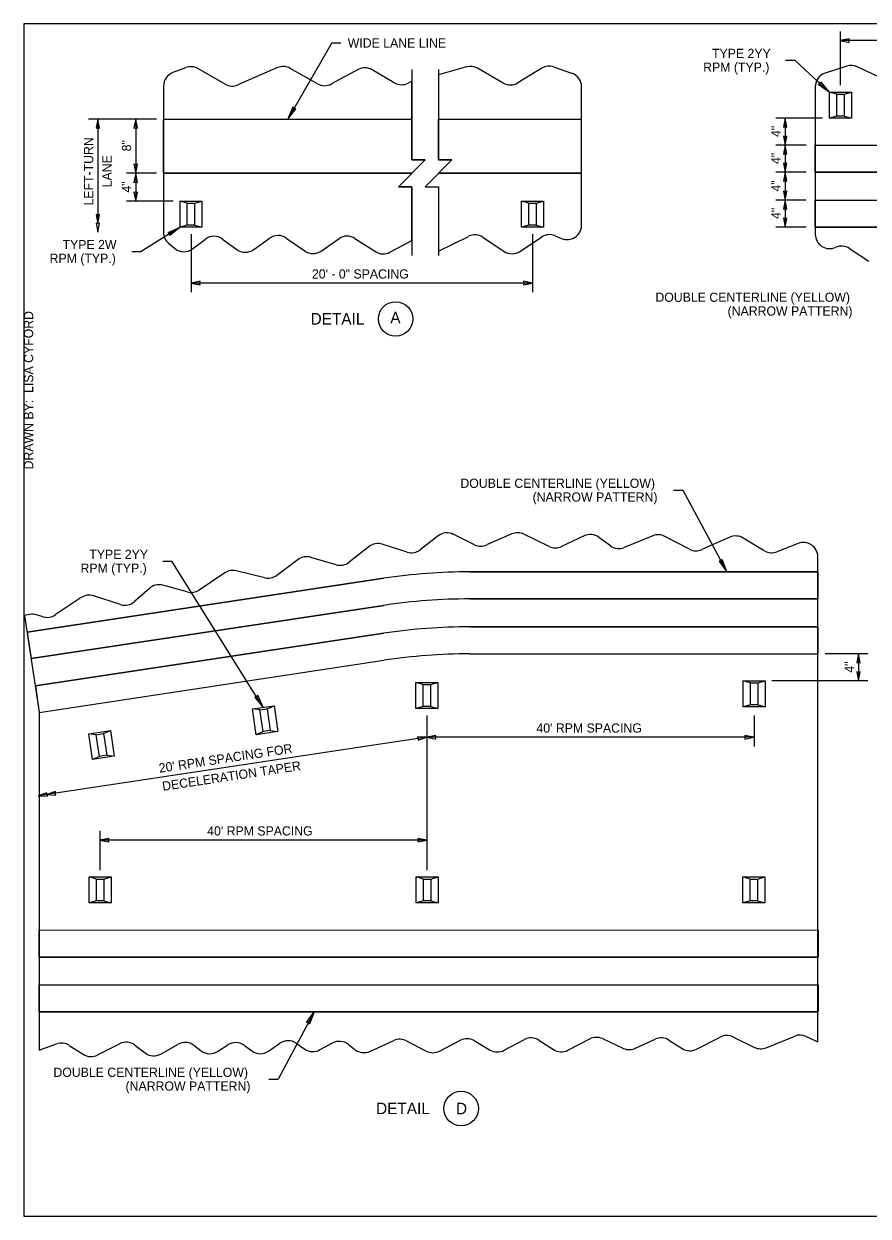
# Model space of a CAD drawing. Extents: x 99862 to 104211, y 98939 to 105076.
# Drawn here: x 99862 to 101332, y 103000 to 105076 of the extents above; entities that cross this region are included whole.
import ezdxf

# ---------------------------------------------------------------- set-up
doc = ezdxf.new("R2010")
doc.units = 0
for name, color, linetype in [('Level 1', 7, 'Continuous'), ('Level 10', 7, 'Continuous'), ('Level 15', 7, 'Continuous'), ('Level 18', 7, 'Continuous'), ('Level 20', 7, 'Continuous'), ('Level 22', 7, 'Continuous'), ('Level 50', 7, 'Continuous'), ('Level 60', 7, 'Continuous'), ('Level 62', 7, 'Continuous'), ('Level 9', 7, 'Continuous')]:
    doc.layers.add(name, color=color, linetype=linetype)

msp = doc.modelspace()

# ---------------------------------------------------------------- linework, layer by layer
at = {"layer": 'Level 1'}
msp.add_lwpolyline([(99862, 102999.5), (103151, 102999.5), (103151, 105075.5), (99862, 105075.5)], close=True, dxfattribs=at)
at = {"layer": 'Level 10'}
for p, q in [((100105, 104909.5), (100537.2, 104909.5)), ((100105, 104815.3), (100105, 104909.5)), ((100583.7, 104909.5), (100832.8, 104909.6)), ((100537.2, 104815.3), (100105, 104815.3)), ((100832.8, 104815.3), (100583.7, 104815.3)), ((101239.7, 104768.6), (101541.9, 104768.7)), ((101239.7, 104721.5), (101239.7, 104768.6)), ((101541.9, 104721.6), (101239.7, 104721.5)), ((100638.1, 104074.2), (101245, 104074.3)), ((100638.1, 103978.6), (101245, 103978.7)), ((99888.7, 103497.7), (101245, 103497.8)), ((99888.7, 103450.8), (99888.7, 103497.7)), ((101245, 103497.8), (101245, 103450.6)), ((100679.8, 103450.7), (99888.7, 103450.8)), ((101245, 103450.6), (100679.8, 103450.7)), ((99888.7, 103402.1), (101245, 103402.2)), ((99888.7, 103355), (99888.7, 103402.1)), ((101245, 103402.2), (101245, 103355.1)), ((101245, 103355.1), (99888.7, 103355))]:
    msp.add_line(p, q, dxfattribs=at)
for points in [[(100537.2, 104909.5), (100537.2, 104838.5), (100560.4, 104838.5), (100537.2, 104815.3)], [(100583.7, 104815.3), (100606.9, 104838.5), (100583.7, 104838.5), (100583.7, 104909.5)], [(101245, 104074.3), (101245, 104121.4), (100638.1, 104121.3)], [(100488.8, 104110.1), (99867.6, 104016.3), (99874.6, 103970.2), (100488.8, 104063)], [(100488.8, 104014.5), (99881.8, 103922.8), (99888.7, 103876.7), (100488.8, 103967.4)], [(101245, 103978.7), (101245, 104025.8), (100638.1, 104025.7)]]:
    msp.add_lwpolyline(points, dxfattribs=at)
msp.add_lwpolyline([(101239.7, 104864.2), (101541.9, 104864.3), (101541.9, 104864), (101541.9, 104850), (101565.1, 104850), (101532.3, 104817.2), (101239.7, 104817.1)], close=True, dxfattribs=at)
for centre in [(100638.2, 103121.3), (100638.2, 103074.2), (100638.2, 103025.7), (100638.2, 102978.6)]:
    msp.add_arc(centre, 1000, 90.0065, 98.5919, dxfattribs=at)
at = {"layer": 'Level 15'}
for p, q in [((101282.9, 105062.4), (101282.9, 104968.6)), ((101852.2, 105046.4), (101282.9, 105046.4)), ((100397.7, 105042.2), (100321.1, 104909.5)), ((100397.7, 105042.2), (100413.7, 105042.2)), ((101187.9, 105012), (101203.9, 105012)), ((101263.8, 104956.7), (101203.9, 105012)), ((100093, 104909.5), (99974.5, 104909.5)), ((99990.5, 104909.5), (99990.5, 104727.8)), ((100056.5, 104909.5), (100056.5, 104815.3)), ((101252.4, 104911.3), (101171.2, 104911.3)), ((101187.2, 104911.3), (101187.2, 104864.2)), ((101223.7, 104864.2), (101171.2, 104864.2)), ((101187.2, 104864.2), (101187.2, 104817.1)), ((100093, 104815.3), (100040.5, 104815.3)), ((100056.5, 104815.3), (100056.5, 104766.8)), ((101223.7, 104817.1), (101171.2, 104817.1)), ((101187.2, 104817.1), (101187.2, 104768.6)), ((100121.7, 104766.8), (100040.5, 104766.8)), ((101223.7, 104768.6), (101171.2, 104768.6)), ((101187.2, 104768.6), (101187.2, 104721.5)), ((100133.7, 104721.5), (100066, 104679.2)), ((101223.7, 104721.5), (101171.2, 104721.5)), ((100152.8, 104709.5), (100152.8, 104608.1)), ((100747.3, 104709.5), (100747.3, 104608.1)), ((100050, 104679.2), (100066, 104679.2)), ((100747.3, 104624.1), (100152.8, 104624.1)), ((100993.1, 104263.6), (101009.1, 104263.6)), ((101009.1, 104263.6), (101085.8, 104121.4)), ((100103.7, 104139.8), (100119.7, 104139.8)), ((100278.4, 103885.4), (100119.7, 104139.8)), ((101331, 103978.7), (101257, 103978.7)), ((101315, 103978.7), (101315, 103931.6)), ((101331, 103931.6), (101164.3, 103931.6)), ((100563.2, 103871.4), (100563.2, 103602.1)), ((101133.2, 103871.4), (101133.2, 103817.4)), ((100563.2, 103833.4), (99886.8, 103731.2)), ((101132.6, 103833.4), (100563.2, 103833.4)), ((101132.6, 103833.4), (100682.2, 103833.4)), ((99993.9, 103670.3), (99993.9, 103602.1)), ((100563.2, 103654.3), (99993.9, 103654.3)), ((100367.5, 103355), (100304.4, 103238)), ((100288.4, 103238), (100304.4, 103238))]:
    msp.add_line(p, q, dxfattribs=at)
for points in [[(101282.9, 105046.4), (101298.6, 105043.3), (101297.9, 105046.4), (101298.6, 105049.4)], [(101263.8, 104956.7), (101245, 104970), (101247.8, 104971.5), (101249, 104974.4)], [(100321.1, 104909.5), (100335.1, 104927.8), (100332, 104928.4), (100329.9, 104930.8)], [(99990.5, 104909.5), (99987.4, 104893.7), (99990.5, 104894.5), (99993.6, 104893.7)], [(100056.5, 104909.5), (100053.4, 104893.7), (100056.5, 104894.5), (100059.6, 104893.7)], [(101187.2, 104911.3), (101184.1, 104895.6), (101187.2, 104896.3), (101190.3, 104895.6)], [(101187.2, 104864.2), (101190.3, 104880), (101187.2, 104879.2), (101184.1, 104880)], [(101187.2, 104864.2), (101184.1, 104848.5), (101187.2, 104849.2), (101190.3, 104848.5)], [(100056.5, 104815.3), (100059.6, 104831), (100056.5, 104830.3), (100053.4, 104831)], [(101187.2, 104817.1), (101190.3, 104832.9), (101187.2, 104832.1), (101184.1, 104832.9)], [(100056.5, 104815.3), (100053.4, 104799.5), (100056.5, 104800.3), (100059.6, 104799.5)], [(101187.2, 104817.1), (101184.1, 104801.4), (101187.2, 104802.1), (101190.3, 104801.4)], [(100056.5, 104766.8), (100059.6, 104782.5), (100056.5, 104781.8), (100053.4, 104782.5)], [(101187.2, 104768.6), (101190.3, 104784.4), (101187.2, 104783.6), (101184.1, 104784.4)], [(101187.2, 104768.6), (101184.1, 104752.9), (101187.2, 104753.6), (101190.3, 104752.9)], [(99990.5, 104727.8), (99993.6, 104743.5), (99990.5, 104742.8), (99987.4, 104743.5)], [(101187.2, 104721.5), (101190.3, 104737.3), (101187.2, 104736.5), (101184.1, 104737.3)], [(99990.5, 104712.8), (99993.6, 104728.5), (99990.5, 104727.8), (99987.4, 104728.5)], [(100133.7, 104721.5), (100115.9, 104706.9), (100115.3, 104710), (100112.8, 104712)], [(100152.8, 104624.1), (100168.5, 104621), (100167.8, 104624.1), (100168.5, 104627.2)], [(100747.3, 104624.1), (100731.5, 104627.2), (100732.3, 104624.1), (100731.5, 104621)], [(101085.8, 104121.4), (101077.6, 104142.9), (101075.5, 104140.6), (101072.3, 104140.1)], [(101315, 103978.7), (101311.9, 103963), (101315, 103963.7), (101318.1, 103963)], [(101315, 103931.6), (101318.1, 103947.3), (101315, 103946.6), (101311.9, 103947.3)], [(100278.4, 103885.4), (100268.9, 103906.4), (100266.9, 103903.9), (100263.8, 103903.2)], [(100563.2, 103833.4), (100547.2, 103834.1), (100548.4, 103831.1), (100548.2, 103828)], [(100563.2, 103833.4), (100579, 103830.3), (100578.2, 103833.4), (100579, 103836.5)], [(101132.6, 103833.4), (101116.9, 103836.5), (101117.6, 103833.4), (101116.9, 103830.3)], [(99901.6, 103733.4), (99917.6, 103732.7), (99916.5, 103735.7), (99916.7, 103738.8)], [(99886.8, 103731.2), (99902.8, 103730.5), (99901.6, 103733.4), (99901.9, 103736.6)], [(99993.9, 103654.3), (100009.6, 103651.2), (100008.9, 103654.3), (100009.6, 103657.3)], [(100563.2, 103654.3), (100547.5, 103657.3), (100548.2, 103654.3), (100547.5, 103651.2)], [(100367.5, 103355), (100359.3, 103333.5), (100357.2, 103335.9), (100354.1, 103336.4)]]:
    msp.add_lwpolyline(points, close=True, dxfattribs=at)
for points in [[(100537.2, 104996.1), (100537.2, 104838.5), (100560.4, 104838.5), (100514, 104792), (100537.2, 104792), (100537.2, 104672.1)], [(100583.7, 104996.1), (100583.7, 104838.5), (100606.9, 104838.5), (100560.4, 104792), (100583.7, 104792), (100583.7, 104672.1)]]:
    msp.add_lwpolyline(points, dxfattribs=at)
at = {"layer": 'Level 18'}
for p, q in [((100105, 104909.5), (100537.2, 104909.5)), ((100583.7, 104909.5), (100832.8, 104909.6)), ((101239.7, 104864.2), (101541.9, 104864.3)), ((100105, 104815.2), (100537.2, 104815.3)), ((100583.7, 104815.3), (100832.8, 104815.3)), ((101239.7, 104817.1), (101532.3, 104817.2)), ((101239.7, 104768.6), (101541.9, 104768.7)), ((101239.7, 104721.5), (101541.9, 104721.6)), ((100638.1, 104121.3), (101245, 104121.4)), ((99867.6, 104016.3), (100488.8, 104110.1)), ((101245, 104074.3), (100638.1, 104074.2)), ((100488.8, 104063), (99874.6, 103970.2)), ((99881.8, 103922.8), (100488.8, 104014.5)), ((100638.1, 104025.7), (101245, 104025.8)), ((99888.7, 103876.7), (100488.8, 103967.4)), ((100638.1, 103978.6), (101245, 103978.7)), ((99888.7, 103497.7), (101245, 103497.8)), ((99888.7, 103450.5), (101245, 103450.6)), ((99888.7, 103402.1), (101245, 103402.2)), ((99888.7, 103355), (101245, 103355.1))]:
    msp.add_line(p, q, dxfattribs=at)
for centre in [(100638.2, 103121.3), (100638.2, 103074.2), (100638.2, 103025.7), (100638.2, 102978.6)]:
    msp.add_arc(centre, 1000, 90.0065, 98.5919, dxfattribs=at)
at = {"layer": 'Level 22'}
for p, q in [((101277.1, 104953), (101264.4, 104956.6)), ((101289.8, 104953), (101302.5, 104956.6)), ((101277.1, 104914.9), (101264.4, 104911.3)), ((101289.8, 104914.9), (101302.5, 104911.3)), ((100146.4, 104763.2), (100133.7, 104766.8)), ((100159.1, 104763.2), (100171.8, 104766.8)), ((100740.9, 104763.2), (100728.2, 104766.8)), ((100753.6, 104763.2), (100766.3, 104766.8)), ((100146.4, 104725.1), (100133.7, 104721.5)), ((100159.1, 104725.1), (100171.8, 104721.5)), ((100740.9, 104725.1), (100728.2, 104721.5)), ((100753.6, 104725.1), (100766.3, 104721.5)), ((100556.9, 103925.1), (100544.2, 103928.7)), ((100569.6, 103925.1), (100582.3, 103928.7)), ((101126.9, 103928), (101114.2, 103931.6)), ((101139.6, 103928), (101152.3, 103931.6)), ((100285.2, 103882.8), (100297.3, 103888.3)), ((100556.9, 103887), (100544.2, 103883.4)), ((100569.6, 103887), (100582.3, 103883.4)), ((101126.9, 103889.9), (101114.2, 103886.3)), ((101139.6, 103889.9), (101152.3, 103886.3)), ((100272.7, 103880.9), (100259.6, 103882.6)), ((100000.4, 103839.6), (100012.4, 103845)), ((100278.4, 103843.3), (100266.3, 103837.8)), ((100290.9, 103845.2), (100304, 103843.5)), ((99987.9, 103837.7), (99974.8, 103839.3)), ((99993.6, 103800), (99981.5, 103794.6)), ((100006.1, 103801.9), (100019.2, 103800.3)), ((99988.2, 103586.5), (99975.5, 103590.1)), ((100000.9, 103586.5), (100013.6, 103590.1)), ((100557.5, 103586.5), (100544.8, 103590.1)), ((100570.2, 103586.5), (100582.9, 103590.1)), ((101126.2, 103586.5), (101113.5, 103590.1)), ((101138.9, 103586.5), (101151.6, 103590.1)), ((99988.2, 103548.4), (99975.5, 103544.9)), ((100000.9, 103548.4), (100013.6, 103544.9)), ((100557.5, 103548.4), (100544.8, 103544.9)), ((100570.2, 103548.4), (100582.9, 103544.9)), ((101126.2, 103548.4), (101113.5, 103544.9)), ((101138.9, 103548.4), (101151.6, 103544.9))]:
    msp.add_line(p, q, dxfattribs=at)
for points in [[(101264.4, 104956.6), (101302.5, 104956.6), (101302.5, 104911.3), (101264.4, 104911.3)], [(101277.1, 104953), (101289.8, 104953), (101289.8, 104914.9), (101277.1, 104914.9)], [(100133.7, 104766.8), (100171.8, 104766.8), (100171.8, 104721.5), (100133.7, 104721.5)], [(100146.4, 104763.2), (100159.1, 104763.2), (100159.1, 104725.1), (100146.4, 104725.1)], [(100728.2, 104766.8), (100766.3, 104766.8), (100766.3, 104721.5), (100728.2, 104721.5)], [(100740.9, 104763.2), (100753.6, 104763.2), (100753.6, 104725.1), (100740.9, 104725.1)], [(100544.2, 103928.7), (100582.3, 103928.7), (100582.3, 103883.4), (100544.2, 103883.4)], [(100556.9, 103925.1), (100569.6, 103925.1), (100569.6, 103887), (100556.9, 103887)], [(101114.2, 103931.6), (101152.3, 103931.6), (101152.3, 103886.3), (101114.2, 103886.3)], [(101126.9, 103928), (101139.6, 103928), (101139.6, 103889.9), (101126.9, 103889.9)], [(100259.6, 103882.6), (100297.3, 103888.3), (100304, 103843.5), (100266.3, 103837.8)], [(100272.7, 103880.9), (100285.2, 103882.8), (100290.9, 103845.2), (100278.4, 103843.3)], [(99974.8, 103839.3), (100012.4, 103845), (100019.2, 103800.3), (99981.5, 103794.6)], [(99987.9, 103837.7), (100000.4, 103839.6), (100006.1, 103801.9), (99993.6, 103800)], [(99975.5, 103590.1), (100013.6, 103590.1), (100013.6, 103544.9), (99975.5, 103544.9)], [(99988.2, 103586.5), (100000.9, 103586.5), (100000.9, 103548.4), (99988.2, 103548.4)], [(100544.8, 103590.1), (100582.9, 103590.1), (100582.9, 103544.9), (100544.8, 103544.9)], [(100557.5, 103586.5), (100570.2, 103586.5), (100570.2, 103548.4), (100557.5, 103548.4)], [(101113.5, 103590.1), (101151.6, 103590.1), (101151.6, 103544.9), (101113.5, 103544.9)], [(101126.2, 103586.5), (101138.9, 103586.5), (101138.9, 103548.4), (101126.2, 103548.4)]]:
    msp.add_lwpolyline(points, close=True, dxfattribs=at)
at = {"layer": 'Level 50'}
for points in [[(100143.4, 104999.2), (100121.1, 104990.7)], [(100212, 104970.4), (100164.7, 104997.6)], [(100303.3, 104999.3), (100234.5, 104969.2)], [(100372.9, 104971.1), (100325.7, 104998)], [(100443.6, 104995.9), (100397.3, 104970.8)], [(100506.6, 104972.9), (100468.2, 104995.5)], [(100583.7, 104986.5), (100583.7, 104838.5), (100606.9, 104838.5), (100560.4, 104792), (100583.7, 104792), (100583.7, 104679.8), (100636.1, 104705.5)], [(100632.2, 105000.5), (100583.7, 104986.5)], [(100696.4, 104972.4), (100651.6, 104998.1)], [(100763.4, 104998.1), (100721.8, 104972.7)], [(100816.1, 104989.3), (100784.7, 105000.3)], [(101294.6, 105001.7), (101257.2, 104989.9)], [(101379, 104969.8), (101312.6, 105000.5)], [(100105, 104967.4), (100105, 104712.5)], [(100537.2, 104698.1), (100537.2, 104792), (100514, 104792), (100560.4, 104838.5), (100537.2, 104838.5), (100537.2, 104975.8), (100531.1, 104972.5)], [(100832.8, 104724.8), (100832.8, 104965.8)], [(101239.7, 104966), (101239.7, 104709.1)], [(100113.8, 104693.4), (100124.2, 104684.7)], [(100155.3, 104683.7), (100178, 104700.7)], [(100207.8, 104700.8), (100232.5, 104682.6)], [(100262, 104682.4), (100289.6, 104702.3)], [(100318.5, 104702.5), (100350.7, 104680)], [(100379.3, 104679.9), (100410.5, 104701.5)], [(100438.3, 104701.9), (100473.8, 104678.9)], [(100499.1, 104677.8), (100537.2, 104698.1)], [(100661, 104703.9), (100697.8, 104679.3)], [(100725.6, 104679.3), (100763.1, 104704.3)], [(100786.8, 104706.5), (100798, 104701.8)], [(101299.2, 104684.5), (101332.9, 104662.5)], [(100583.2, 104184), (100552, 104159.8)], [(100646.5, 104168.6), (100609.5, 104186.7)], [(100711.5, 104187.3), (100667.5, 104168.1)], [(100776.5, 104165.4), (100732.5, 104186.8)], [(100837.3, 104183.9), (100798.1, 104165.3)], [(100882.9, 104166.7), (100862.8, 104181.4)], [(100956.9, 104184.1), (100907.1, 104163.8)], [(101020.5, 104160.8), (100978, 104183.1)], [(101091.2, 104181.6), (101042.3, 104160)], [(101151, 104158.1), (101114.2, 104180.2)], [(100462.7, 104165.3), (100428.1, 104138)], [(100529.1, 104155.8), (100485.7, 104169.5)], [(101209.9, 104170.8), (101173, 104156.3)], [(100339.5, 104142.8), (100302, 104115.2)], [(100405.6, 104133.7), (100361.3, 104146.6)], [(101244.1, 103303.2), (101244.1, 104147.5)], [(100211.5, 104119.5), (100166.8, 104089.6)], [(100281.3, 104111.1), (100231.3, 104123.1)], [(100080.3, 104092.6), (100054.4, 104069.5)], [(100146.3, 104086.3), (100103.6, 104098.1)], [(99961.7, 104076.6), (99916.3, 104046.3)], [(100030, 104064.3), (99983.3, 104079.5)], [(99872.1, 104047.2), (99862.8, 104045.5), (99888.7, 103876.8), (99888.7, 103288.6), (99918.9, 103299.4)], [(99895.4, 104043.1), (99883.6, 104046.6)], [(100463.9, 103286.4), (100506.1, 103305.3)], [(100527.8, 103304.8), (100562.5, 103286.9)], [(100585.4, 103286.9), (100621.8, 103305.7)], [(100645.9, 103305.1), (100673.8, 103288.8)], [(100698.1, 103288.3), (100733.2, 103306.9)], [(100758.2, 103305.9), (100784, 103289.5)], [(100808.8, 103288.4), (100847.1, 103308.1)], [(100869, 103308.6), (100905.9, 103291.7)], [(100926.9, 103291.8), (100960.7, 103307.7)], [(100984.9, 103306.1), (101007.9, 103291.3)], [(101032.8, 103290.1), (101074.1, 103311.3)], [(101096.4, 103311.5), (101133.7, 103293.4)], [(101154, 103292.7), (101203.9, 103312.9)], [(101223.6, 103312.5), (101244.1, 103303.2)], [(99940.9, 103296.9), (99965.2, 103281.3)], [(99990.1, 103280.1), (100028.4, 103299.7)], [(100055, 103297.3), (100072.7, 103283.7)], [(100100.4, 103281.8), (100130.2, 103298.8)], [(100157.6, 103297.1), (100170.6, 103287.3)], [(100199.1, 103286.3), (100217, 103297.7)], [(100245.1, 103297), (100258.8, 103287.2)], [(100287.6, 103286.9), (100307.4, 103300.6)], [(100335.7, 103300.7), (100350.8, 103290.4)], [(100376.6, 103289), (100399.2, 103301)], [(100426.2, 103298.7), (100438.3, 103289.4)]]:
    msp.add_lwpolyline(points, dxfattribs=at)
for centre, start, end in [((100130, 104967.4), 110.8542, 180), ((100152.3, 104975.9), 60.1799, 110.8542), ((100313.3, 104976.3), 60.2551, 113.5747), ((100455.5, 104973.9), 59.6013, 118.4212), ((100639.1, 104976.5), 60.1011, 106.1443), ((100776.4, 104976.8), 70.6557, 121.3995), ((100807.8, 104965.8), 0, 70.6557), ((101264.7, 104966), 107.5563, 180), ((101302.1, 104977.9), 65.1673, 107.5563), ((100224.5, 104992.1), 240.1799, 293.5747), ((100385.4, 104992.8), 240.2551, 298.4212), ((100519.3, 104994.5), 239.6013, 298.1786), ((100708.8, 104994.1), 240.1011, 301.3995), ((100807.8, 104724.8), 246.8858, 0), ((100130, 104712.5), 180, 229.6859), ((100193, 104680.7), 53.5556, 126.8699), ((100304.2, 104682), 55.0607, 125.7761), ((100424.7, 104680.9), 57.0306, 124.6111), ((100647.1, 104683.1), 56.3099, 116.1049), ((100777, 104683.5), 66.8858, 123.6901), ((101264.7, 104709.1), 180, 294.5655), ((100140.3, 104703.7), 229.6859, 306.8699), ((100247.3, 104702.7), 233.5556, 305.7761), ((100365.1, 104700.5), 235.0607, 304.6111), ((100487.4, 104699.9), 237.0306, 297.9971), ((100711.7, 104700.1), 236.3099, 303.6901), ((101285.5, 104663.6), 56.8644, 114.5655), ((100598.5, 104164.2), 63.9151, 127.7634), ((100721.5, 104164.4), 64.0256, 113.5523), ((100848, 104161.3), 53.8418, 115.3462), ((100966.4, 104161), 62.2415, 112.249), ((101101.3, 104158.8), 59.0362, 113.8387), ((100478.2, 104145.7), 72.4076, 128.2338), ((100536.7, 104179.6), 252.4076, 307.7634), ((100657.5, 104191), 243.9151, 293.5523), ((100787.4, 104187.9), 244.0256, 295.3462), ((100897.7, 104186.9), 233.8418, 292.249), ((101032.2, 104182.9), 242.2415, 293.8387), ((101163.9, 104179.6), 239.0362, 291.4305), ((101219.1, 104147.5), 0, 111.4305), ((100354.3, 104122.7), 73.6861, 126.3268), ((100412.6, 104157.7), 253.6861, 308.2338), ((100225.4, 104098.8), 76.5084, 123.7572), ((100287.2, 104135.4), 256.5084, 306.3268), ((100096.9, 104073.9), 74.6237, 131.7603), ((99975.6, 104055.8), 71.9657, 123.6901), ((100152.9, 104110.4), 254.6237, 303.7572), ((100037.7, 104088.1), 251.9657, 311.7603), ((99876.5, 104022.6), 73.6515, 100.2702), ((99902.5, 104067.1), 253.6515, 303.6901), ((100039.8, 103277.5), 52.4314, 117.1497), ((100142.6, 103277.1), 53.1301, 119.7449), ((100321.6, 103280), 55.7843, 124.5923), ((100411, 103278.9), 52.3058, 118.0725), ((100516.3, 103282.5), 62.7538, 114.2277), ((100633.3, 103283.5), 59.8586, 117.2811), ((100744.8, 103284.8), 57.6526, 117.8241), ((100858.6, 103285.8), 65.4328, 117.1811), ((100971.4, 103285.1), 57.2648, 115.2011), ((101085.5, 103289), 64.0935, 117.1497), ((101213.3, 103289.8), 65.5268, 112.0362), ((99927.4, 103275.9), 57.2648, 109.7606), ((99978.7, 103302.3), 237.2648, 297.1497), ((100088, 103303.5), 232.4314, 299.7449), ((100185.6, 103307.3), 233.1301, 302.7352), ((100230.5, 103276.7), 54.2461, 122.7352), ((100273.4, 103307.4), 234.2461, 304.5923), ((100364.9, 103311), 235.7843, 298.0725), ((100453.6, 103309.2), 232.3058, 294.2277), ((100573.9, 103309.1), 242.7538, 297.2811), ((100686.4, 103310.4), 239.8586, 297.8241), ((100797.4, 103310.6), 237.6526, 297.1811), ((100916.3, 103314.4), 245.4328, 295.2011), ((101021.4, 103312.4), 237.2648, 297.1497), ((101144.6, 103315.9), 244.0935, 292.0362)]:
    msp.add_arc(centre, 25, start, end, dxfattribs=at)
at = {"layer": 'Level 60'}
msp.add_line((99862, 102999.5), (99862, 102999.5), dxfattribs=at)
at = {"layer": 'Level 9'}
for centre in [(100509, 104561.7), (100623.1, 103186.9)]:
    msp.add_circle(centre, 30, dxfattribs=at)

# ---------------------------------------------------------------- texts
at = {"layer": 'Level 20'}
for s, height, p in [('WIDE LANE LINE', 16, (100425.7, 105034.2)), ('TYPE 2YY', 16, (101059.9, 105016)), ('RPM (TYP.)', 16, (101044.5, 104992)), ('TYPE 2W', 16, (99929.2, 104683.2)), ('RPM (TYP.)', 16, (99906.6, 104659.2)), ('DOUBLE CENTERLINE (YELLOW)', 16, (100961.3, 104591.5)), ('DETAIL', 20, (100361, 104551.9)), ('A', 20, (100499.8, 104554.1)), ('(NARROW PATTERN)', 16, (101087, 104567.5)), ('DOUBLE CENTERLINE (YELLOW)', 16, (100621.8, 104267.6)), ('(NARROW PATTERN)', 16, (100747.5, 104243.6)), ('TYPE 2YY', 16, (99975.7, 104143.8)), ('RPM (TYP.)', 16, (99960.4, 104119.8)), ('DOUBLE CENTERLINE (YELLOW)', 16, (99913.2, 103242)), ('(NARROW PATTERN)', 16, (100038.8, 103218)), ('DETAIL', 20, (100475, 103177.1)), ('D', 20, (100614.1, 103176.9))]:
    msp.add_text(s, height=height, dxfattribs=at).set_placement(p)
for s, rotation, p in [('4"', 90, (101179.2, 104878.4)), ('LEFT-TURN', 90, (99982.5, 104759.2)), ('8"', 90, (100048.5, 104853.6)), ('LANE', 90, (100014.5, 104790.8)), ('4"', 90, (101179.2, 104831.3)), ('4"', 90, (100048.5, 104781.7)), ('4"', 90, (101179.2, 104783.5)), ('4"', 90, (101179.2, 104735.7)), ('20\' - 0" SPACING', 360, (100363.3, 104632.1)), ('4"', 90, (101307, 103945.8)), ("40' RPM SPACING", 360, (100754.2, 103841.4)), ("20' RPM SPACING FOR", 8.5919, (100098.1, 103771.4)), ('DECELERATION TAPER', 8.5919, (100104, 103739.9)), ("40' RPM SPACING", 360, (100181, 103662.3))]:
    msp.add_text(s, height=16, rotation=rotation, dxfattribs=at).set_placement(p)
at = {"layer": 'Level 62'}
msp.add_text('DRAWN BY:  LISA CYFORD', height=16, rotation=90, dxfattribs=at).set_placement((99878, 104299.7))

doc.saveas('drawing.dxf')
